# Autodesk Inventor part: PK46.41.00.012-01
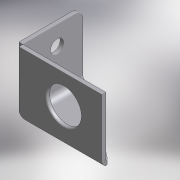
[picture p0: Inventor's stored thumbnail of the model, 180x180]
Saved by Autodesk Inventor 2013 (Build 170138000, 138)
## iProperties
Created: 2005-07
Part Number: PK46.41.00.012-01
Material: Steel, Mild
Document SubType Name: Листовой материал
Designer: PVitaliy
Manufacturer: Standard
Standards Organization: Custom
Density: 7.86 g/cm^3
Author: PVitaliy
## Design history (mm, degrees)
derived "PK46.41.00.114.ipt"
body "Solid1"
tag "TaggingFeature2"
feature "DerivedBody::PK46.41.00.114.ipt" dims "d0" = 10
